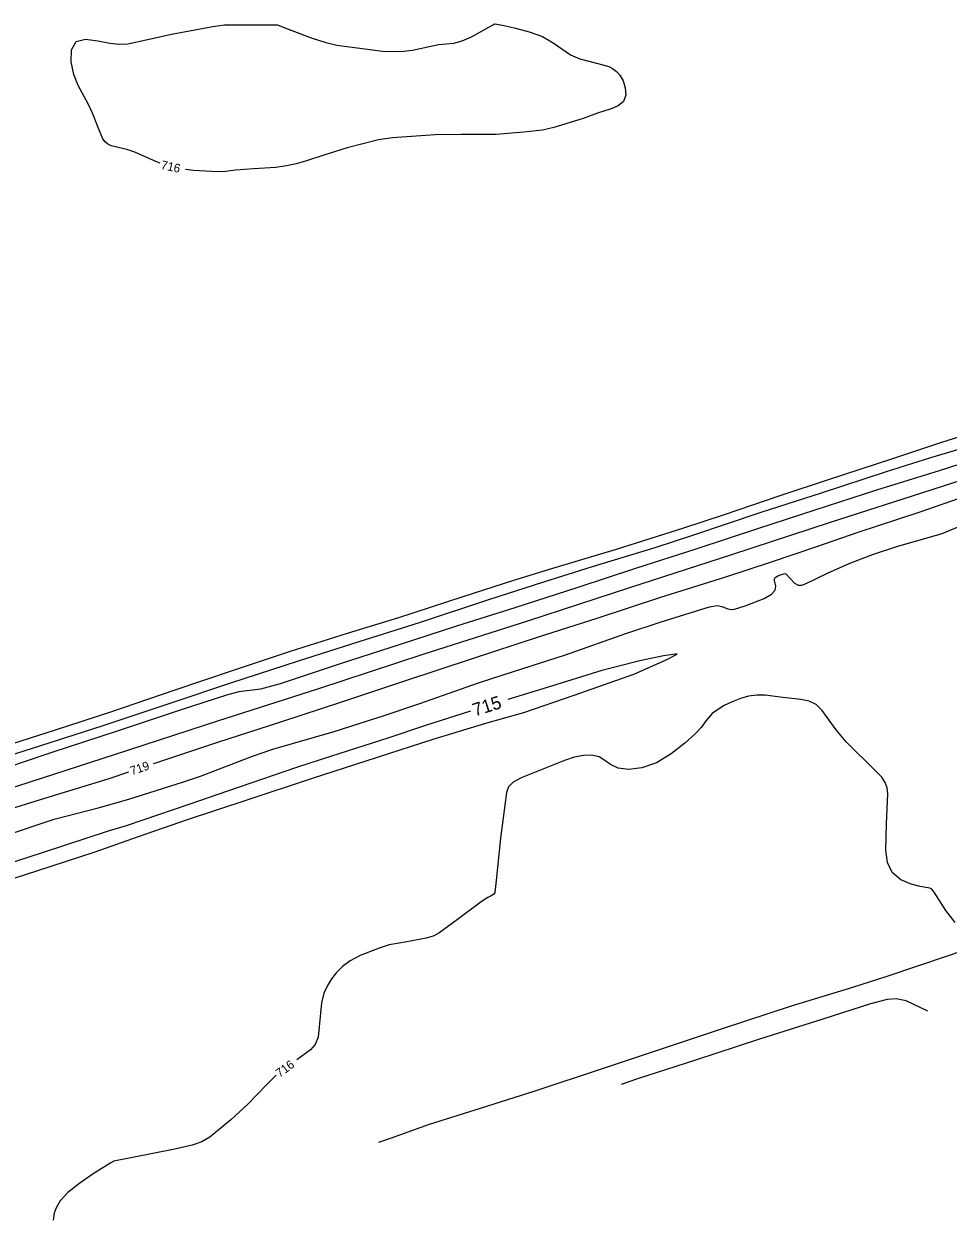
# Model space of a CAD drawing. Extents: x -468563856 to 36492962, y -306094093 to 11899197.
# Drawn here: x 1820533 to 1820960, y 530398 to 530950 of the extents above; entities that cross this region are included whole.
import ezdxf

# ---------------------------------------------------------------- set-up
doc = ezdxf.new("R2010")
doc.units = 0
for name, color, linetype in [('DT_X_Contour_Minor', 7, 'Continuous'), ('Level 14', 7, 'Continuous'), ('Level 19', 7, 'Continuous')]:
    doc.layers.add(name, color=color, linetype=linetype)

msp = doc.modelspace()

# ---------------------------------------------------------------- linework, layer by layer
at = {"layer": 'DT_X_Contour_Minor'}
for points in [[(1820596.12, 530885.73), (1820594.38, 530886.35), (1820584.38, 530890.74), (1820580.7, 530891.99), (1820573.55, 530893.71), (1820571.93, 530894.51), (1820570.66, 530895.56), (1820569.68, 530896.93), (1820567.82, 530901.4), (1820564.84, 530908.86), (1820562.82, 530913.07), (1820558.2, 530921.6), (1820556.25, 530926.66), (1820555.05, 530932.51), (1820555.19, 530938.05), (1820557.3, 530941.85), (1820561.68, 530942.94), (1820567.32, 530942.22), (1820572.89, 530941.07), (1820577.39, 530940.58), (1820581.21, 530940.82), (1820589.67, 530942.62), (1820601.39, 530945.25), (1820620.49, 530948.78), (1820625.87, 530949.5), (1820645.54, 530949.56), (1820650.3, 530949.5), (1820654.46, 530947.92), (1820666.26, 530943.43), (1820672.62, 530941.36), (1820677.75, 530940.19), (1820700, 530937.24), (1820708.57, 530937.45), (1820712.68, 530937.94), (1820724.58, 530940.54), (1820731.72, 530941.17), (1820735.58, 530942.1), (1820739.86, 530944.01), (1820750.6, 530949.98), (1820755, 530949.18), (1820760.19, 530948.07), (1820766.53, 530946.39), (1820772.64, 530944.12), (1820777.53, 530941.32), (1820785.55, 530935.78), (1820789.94, 530933.87), (1820798.26, 530931.67), (1820803.27, 530930.27), (1820805.04, 530929.37), (1820806.78, 530928.09), (1820808.43, 530926.27), (1820809.85, 530923.76), (1820810.84, 530920.54), (1820811.05, 530917.14), (1820810.05, 530914.19), (1820807.63, 530912.16), (1820804.36, 530910.85), (1820797.99, 530908.82), (1820791.39, 530906.35), (1820777.89, 530902.22), (1820772.62, 530900.91), (1820764.03, 530899.98), (1820751.26, 530898.92), (1820735.05, 530898.92), (1820723.16, 530898.84), (1820703.39, 530897.34), (1820696.86, 530896.44), (1820682.52, 530892.76), (1820671.69, 530889.46), (1820663.24, 530886.61), (1820658.95, 530885.42), (1820654.37, 530884.44), (1820649.47, 530883.74), (1820639.21, 530883.14), (1820630.9, 530882.52), (1820625.2, 530881.78), (1820619.8, 530881.81), (1820611.46, 530882.36), (1820607.77, 530882.8)], [(1820994.59, 530768.11), (1820970.12, 530761), (1820956.88, 530756.85), (1820934.19, 530749.31), (1820904.48, 530739.54), (1820882.62, 530732.37), (1820856.03, 530723.29), (1820837.77, 530717.22), (1820806.61, 530707.35), (1820778.8, 530699.04), (1820759.24, 530693.04), (1820735.87, 530685.51), (1820706.09, 530675.91), (1820682.51, 530668.65), (1820656.18, 530660.32), (1820629.75, 530651.53), (1820602.88, 530642.43), (1820572.65, 530632.09), (1820547.68, 530624.01), (1820519.59, 530615.03)], [(1820526.16, 530612.23), (1820552.63, 530620.56), (1820569.76, 530626.1), (1820601.63, 530636.82), (1820628.71, 530645.86), (1820659.93, 530656.08), (1820688.02, 530664.97), (1820715.8, 530673.68), (1820747.85, 530684.27), (1820773.3, 530692.55), (1820795.74, 530699.58), (1820824.62, 530708.33), (1820842.02, 530714.06), (1820873.61, 530724.62), (1820901.46, 530733.55), (1820931.55, 530743.33), (1820951.95, 530749.83), (1820983.67, 530759.18)], [(1820975, 530749.89), (1820974.39, 530749.69), (1820955.82, 530743.7), (1820926.89, 530734.79), (1820898.46, 530725.6), (1820872.39, 530717.07), (1820843.48, 530707.6), (1820815.52, 530698.58), (1820788.91, 530689.89), (1820759.92, 530680.44), (1820733.01, 530671.94), (1820706.96, 530663.61), (1820679.3, 530654.6), (1820651.55, 530645.41), (1820642.4, 530642.94), (1820632.42, 530641.65), (1820626.79, 530640.14), (1820605.78, 530633.36), (1820576.19, 530623.56), (1820546.48, 530613.85), (1820531, 530608.69), (1820527.63, 530607.45)], [(1820593.08, 530608.64), (1820594.09, 530608.98), (1820622.72, 530618.45), (1820651.86, 530627.86), (1820680.46, 530637.24), (1820709.06, 530646.75), (1820740.35, 530657.14), (1820770.27, 530666.89), (1820797.88, 530675.76), (1820827.26, 530685.33), (1820857.33, 530694.81), (1820878.43, 530701.68), (1820899.35, 530708.82), (1820918.33, 530715.38), (1820946.64, 530724.64), (1820976.29, 530735.01)], [(1820524.27, 530575.19), (1820547.11, 530582.88), (1820568.11, 530588.35), (1820581.64, 530592.15), (1820606.94, 530600.17), (1820614.81, 530602.78), (1820638.81, 530611.99), (1820648.07, 530615.22), (1820676.38, 530623.38), (1820699.11, 530630.63), (1820716.04, 530636.25), (1820743.1, 530645.81), (1820754.91, 530649.72), (1820783.3, 530658.72), (1820811.13, 530668.65), (1820826.94, 530673.85), (1820849.83, 530680.88), (1820853.33, 530681.48), (1820855.45, 530681.02), (1820858.29, 530680.07), (1820859.83, 530679.78), (1820861.35, 530679.85), (1820866.24, 530681.36), (1820874.93, 530684.75), (1820878.45, 530686.75), (1820880.08, 530688.7), (1820880.31, 530690.47), (1820879.7, 530693.06), (1820879.73, 530693.88), (1820880.1, 530694.49), (1820881.69, 530695.39), (1820884.6, 530696.33), (1820885.01, 530696.11), (1820889.01, 530691.83), (1820890.69, 530690.96), (1820892.41, 530690.95), (1820894.4, 530691.7), (1820904.23, 530696.54), (1820914.25, 530700.9), (1820925.49, 530705.27), (1820936.19, 530708.73), (1820957.18, 530714.85), (1820967.16, 530718.95)], [(1820509.49, 530549.57), (1820539.19, 530559.14), (1820566.07, 530567.89), (1820586.07, 530574.9), (1820608.77, 530582.74), (1820636.21, 530591.82), (1820666.4, 530601.84), (1820696.43, 530611.57), (1820722.11, 530619.81), (1820746.51, 530627.19), (1820764.07, 530632.19), (1820787.28, 530640.14), (1820814.77, 530649.86), (1820829.42, 530656.28), (1820834.81, 530659.15), (1820834.04, 530659.15), (1820828.51, 530658.38), (1820817.57, 530655.99), (1820800.02, 530651.54), (1820774.8, 530643.72), (1820756.6, 530638.18)], [(1820963.16, 530535.19), (1820958.82, 530540.74), (1820953.43, 530549.3), (1820952.25, 530550.72), (1820951.55, 530551.1), (1820947.06, 530551.8), (1820942.9, 530552.92), (1820938.13, 530554.97), (1820934.13, 530558.27), (1820931.91, 530562.97), (1820931.16, 530568.66), (1820931.48, 530580.77), (1820932.11, 530594.62), (1820931.81, 530597.47), (1820930.94, 530599.89), (1820929.32, 530602.25), (1820926.74, 530605), (1820912.91, 530618.69), (1820908.18, 530624.11), (1820901.8, 530633.03), (1820899.02, 530635.89), (1820895.73, 530637.44), (1820891.96, 530638.13), (1820883.67, 530639.14), (1820875.41, 530640.19), (1820871.56, 530640.16), (1820867.84, 530639.63), (1820864.09, 530638.6), (1820860.25, 530637.11), (1820856.58, 530635.32), (1820853.42, 530633.44), (1820851.04, 530631.63), (1820848.2, 530628.49), (1820845.9, 530625.28), (1820843.12, 530622.34), (1820838.35, 530617.95), (1820832.13, 530613.06), (1820825.27, 530608.93), (1820818.53, 530606.57), (1820812.46, 530605.88), (1820807.55, 530606.54), (1820804.07, 530608.12), (1820801.42, 530610.04), (1820798.76, 530611.65), (1820795.46, 530612.42), (1820791.54, 530612.34), (1820787.25, 530611.5), (1820782.74, 530610.02), (1820762.79, 530601.98), (1820759.05, 530599.98), (1820756.98, 530597.89), (1820756.09, 530595.31), (1820753.33, 530574.11), (1820751.26, 530554.67), (1820750.71, 530549.1), (1820750.18, 530548.25), (1820749.02, 530547.62), (1820747.42, 530546.8), (1820744.27, 530544.74), (1820733.39, 530536.66), (1820724.81, 530530.26), (1820722.18, 530528.87), (1820719.01, 530527.96), (1820709.2, 530526.17), (1820701.92, 530524.9), (1820697.3, 530523.44), (1820688.51, 530519.94), (1820683.91, 530517.57), (1820680.29, 530514.97), (1820677.52, 530512.19), (1820675.29, 530509.27), (1820673.32, 530506.17), (1820671.7, 530502.61), (1820670.59, 530498.21), (1820669.01, 530482.38), (1820667.64, 530478.95), (1820665.49, 530476.51), (1820659.26, 530471.89)], [(1820739.43, 530632.78), (1820718.62, 530626.11), (1820701.76, 530620.43), (1820674.7, 530611.84), (1820659.02, 530606.82), (1820627.65, 530596.01), (1820609.42, 530589.65), (1820580.36, 530579.93), (1820572.52, 530577.51), (1820541.13, 530567.28), (1820513.91, 530558.43), (1820483.19, 530548.12), (1820454.82, 530539.23), (1820446.73, 530536.65), (1820415.19, 530525.87), (1820396.62, 530519.72), (1820368.26, 530510.3), (1820345.95, 530503.3), (1820322.25, 530495.81), (1820295.29, 530487.44), (1820270.81, 530479.96), (1820264.78, 530478.05)], [(1820075.51, 530441.43), (1820087.42, 530445.4), (1820115.34, 530454.39), (1820146.83, 530464.12), (1820177.17, 530473.97), (1820205.38, 530483.31), (1820232.14, 530492.46), (1820257.81, 530501.03), (1820281.44, 530508.58), (1820307.79, 530516.82), (1820336.91, 530525.99), (1820366.57, 530535.4), (1820389.44, 530542.78), (1820416.12, 530551.36), (1820441.62, 530559.58), (1820469.44, 530568.53), (1820493.22, 530576.28), (1820523.05, 530586.42), (1820542.91, 530592.65), (1820572.16, 530601.61), (1820581.7, 530604.81)], [(1820697.12, 530433.81), (1820702.92, 530435.91), (1820720.48, 530442.12), (1820743.97, 530449.49), (1820769.31, 530457.58), (1820800.41, 530467.9), (1820830.85, 530478.04), (1820855.3, 530486.23), (1820887.66, 530496.79), (1820915.92, 530505.39), (1820931.79, 530510.46), (1820959.68, 530519.8), (1820984.4, 530528.33), (1821004.64, 530535.17), (1821024.92, 530541.83), (1821050.49, 530550.19), (1821076.84, 530558.79)], [(1820950.53, 530494.32), (1820940.64, 530499.02), (1820936.02, 530499.97), (1820931.81, 530499.68), (1820924.16, 530497.68), (1820902.57, 530490.85), (1820872.44, 530481.21), (1820843.31, 530471.77), (1820816.51, 530463.01), (1820809, 530460.52)], [(1820649.65, 530464.71), (1820645.31, 530460.51), (1820636.43, 530451.24), (1820628.79, 530444.22), (1820619.11, 530436.13), (1820615.35, 530434.04), (1820610.84, 530432.44), (1820602.09, 530430.48), (1820574.78, 530425.12), (1820573.3, 530424.29), (1820565.14, 530419.16), (1820558.98, 530414.95), (1820553.47, 530410.59), (1820549.9, 530406.75), (1820548.03, 530403.59), (1820547.24, 530401.15), (1820546.72, 530397.89)]]:
    msp.add_lwpolyline(points, dxfattribs=at)
at = {"layer": 'Level 14'}
msp.add_lwpolyline([(1821454.26, 530897.29), (1821404.04, 530881.11), (1821354.18, 530865), (1821308.77, 530850.11), (1821260.81, 530834.64), (1821218.05, 530821.11), (1821173.36, 530806.4), (1821126.28, 530791.17), (1821080.2, 530776.27), (1821039.06, 530763.07), (1820994.69, 530748.7), (1820952.46, 530734.98), (1820905.4, 530719.87), (1820859.85, 530704.9), (1820812.8, 530689.68), (1820765.71, 530674.39), (1820717.41, 530658.86), (1820668.82, 530642.99), (1820623, 530628.33), (1820574.95, 530612.67), (1820524.52, 530596.36)], dxfattribs=at)

# ---------------------------------------------------------------- texts
at = {"layer": 'Level 19'}
for s, height, rotation, p in [('716', 4, 347.6192, (1820596.21, 530883.11)), ('715', 6, 17.756, (1820741.47, 530630.28)), ('719', 4, 18.581, (1820583.04, 530603.15)), ('716', 4, 36.5261, (1820651.32, 530463.53))]:
    msp.add_text(s, height=height, rotation=rotation, dxfattribs=at).set_placement(p)

doc.saveas('drawing.dxf')
